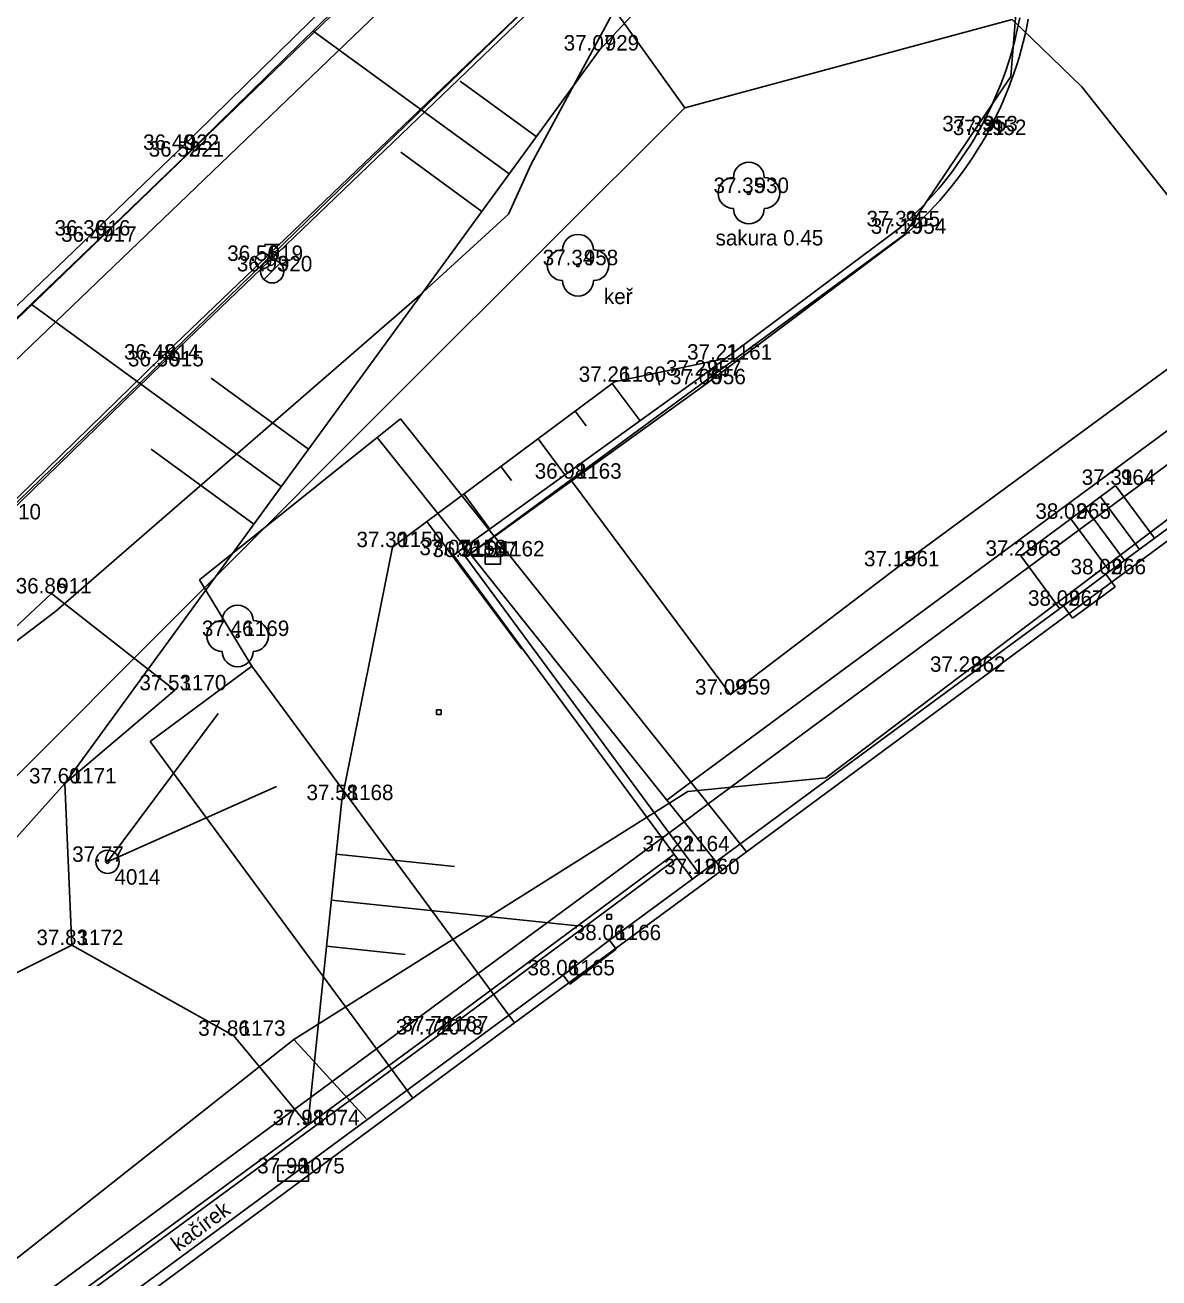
# Model space of a CAD drawing. Extents: x -609709 to -609357, y -1051535 to -1051131.
# Drawn here: x -609603.24 to -609584.85, y -1051267.96 to -1051247.66 of the extents above; entities that cross this region are included whole.
import ezdxf

# ---------------------------------------------------------------- set-up
doc = ezdxf.new("R2010")
doc.units = 0
for name, color, linetype in [('Vrstva 1', 7, 'Continuous'), ('Vrstva 10', 7, 'Continuous'), ('Vrstva 12', 7, 'Continuous'), ('Vrstva 15', 7, 'Continuous'), ('Vrstva 17', 7, 'Continuous'), ('Vrstva 18', 7, 'Continuous'), ('Vrstva 2', 7, 'Continuous'), ('Vrstva 3', 7, 'Continuous'), ('Vrstva 4', 7, 'Continuous'), ('Vrstva 5', 7, 'Continuous'), ('Vrstva 6', 7, 'Continuous'), ('Vrstva 7', 7, 'Continuous'), ('Vrstva 8', 7, 'Continuous'), ('Vrstva 9', 7, 'Continuous')]:
    doc.layers.add(name, color=color, linetype=linetype)

msp = doc.modelspace()

# ---------------------------------------------------------------- linework, layer by layer
at = {"layer": 'Vrstva 1'}
for p, q in [((-609593.93, -1051248.07), (-609593.93, -1051248.07)), ((-609587.79, -1051249.38), (-609587.79, -1051249.38)), ((-609587.65, -1051249.44), (-609587.65, -1051249.44)), ((-609600.74, -1051249.68), (-609600.74, -1051249.68)), ((-609600.66, -1051249.79), (-609600.66, -1051249.79)), ((-609591.5, -1051250.38), (-609591.5, -1051250.38)), ((-609602.18, -1051251.07), (-609602.18, -1051251.07)), ((-609589.05, -1051250.92), (-609589.05, -1051250.92)), ((-609588.95, -1051251.04), (-609588.95, -1051251.04)), ((-609602.08, -1051251.17), (-609602.08, -1051251.17)), ((-609599.38, -1051251.48), (-609599.38, -1051251.48)), ((-609599.23, -1051251.65), (-609599.23, -1051251.65)), ((-609594.27, -1051251.55), (-609594.27, -1051251.55)), ((-609601.06, -1051253.08), (-609601.06, -1051253.08)), ((-609591.96, -1051253.08), (-609591.96, -1051253.08)), ((-609600.99, -1051253.19), (-609600.99, -1051253.19)), ((-609592.27, -1051253.34), (-609592.27, -1051253.34)), ((-609593.68, -1051253.44), (-609593.68, -1051253.44)), ((-609592.2, -1051253.48), (-609592.2, -1051253.48)), ((-609594.4, -1051255.01), (-609594.4, -1051255.01)), ((-609585.56, -1051255.11), (-609585.56, -1051255.11)), ((-609586.28, -1051255.66), (-609586.28, -1051255.66)), ((-609597.28, -1051256.12), (-609597.28, -1051256.12)), ((-609596.27, -1051256.25), (-609596.27, -1051256.25)), ((-609596.09, -1051256.28), (-609596.09, -1051256.28)), ((-609595.65, -1051256.27), (-609595.65, -1051256.27)), ((-609587.09, -1051256.26), (-609587.09, -1051256.26)), ((-609589.06, -1051256.43), (-609589.06, -1051256.43)), ((-609585.71, -1051256.56), (-609585.71, -1051256.56)), ((-609602.81, -1051256.87), (-609602.81, -1051256.87)), ((-609586.4, -1051257.07), (-609586.4, -1051257.07)), ((-609599.79, -1051257.56), (-609599.79, -1051257.56)), ((-609587.99, -1051258.14), (-609587.99, -1051258.14)), ((-609600.81, -1051258.44), (-609600.81, -1051258.44)), ((-609591.8, -1051258.51), (-609591.8, -1051258.51)), ((-609602.59, -1051259.95), (-609602.59, -1051259.95)), ((-609598.1, -1051260.22), (-609598.1, -1051260.22)), ((-609592.65, -1051261.05), (-609592.65, -1051261.05)), ((-609601.9, -1051261.22), (-609601.9, -1051261.22)), ((-609592.3, -1051261.42), (-609592.3, -1051261.42)), ((-609602.48, -1051262.57), (-609602.48, -1051262.57)), ((-609593.76, -1051262.49), (-609593.76, -1051262.49)), ((-609594.51, -1051263.06), (-609594.51, -1051263.06)), ((-609599.85, -1051264.04), (-609599.85, -1051264.04)), ((-609596.65, -1051264.02), (-609596.65, -1051264.02)), ((-609596.56, -1051263.97), (-609596.56, -1051263.97)), ((-609598.65, -1051265.49), (-609598.65, -1051265.49)), ((-609598.89, -1051266.27), (-609598.89, -1051266.27))]:
    msp.add_line(p, q, dxfattribs=at)
at = {"layer": 'Vrstva 10'}
for p, q in [((-609622.18, -1051273.63), (-609589.38, -1051241.83)), ((-609623.53, -1051271.88), (-609592.58, -1051242.01)), ((-609587.25, -1051248.49), (-609587.01, -1051245.46)), ((-609588.98, -1051251.06), (-609587.25, -1051248.49)), ((-609595.63, -1051255.94), (-609588.98, -1051251.06)), ((-609592.44, -1051259.93), (-609583.52, -1051253.35)), ((-609592.16, -1051260.28), (-609583.26, -1051253.71)), ((-609597.53, -1051254.34), (-609597.15, -1051254.04)), ((-609597.15, -1051254.04), (-609595.63, -1051255.94)), ((-609600.41, -1051256.65), (-609597.53, -1051254.34)), ((-609597.53, -1051254.34), (-609596.02, -1051256.23)), ((-609591.54, -1051261.06), (-609582.68, -1051254.52)), ((-609596.02, -1051256.23), (-609595.63, -1051255.94)), ((-609595.63, -1051255.94), (-609592.44, -1051259.93)), ((-609596.02, -1051256.23), (-609592.83, -1051260.22)), ((-609600.41, -1051256.65), (-609599.56, -1051258.05)), ((-609601.21, -1051259.27), (-609599.56, -1051258.05)), ((-609599.56, -1051258.05), (-609595.89, -1051263.03)), ((-609596.565, -1051258.755), (-609596.49, -1051258.755)), ((-609596.565, -1051258.83), (-609596.565, -1051258.755)), ((-609596.49, -1051258.83), (-609596.565, -1051258.83)), ((-609596.49, -1051258.755), (-609596.49, -1051258.83)), ((-609601.21, -1051259.27), (-609597.54, -1051264.25)), ((-609592.83, -1051260.22), (-609592.44, -1051259.93)), ((-609592.44, -1051259.93), (-609592.16, -1051260.28)), ((-609592.83, -1051260.22), (-609592.55, -1051260.57)), ((-609592.55, -1051260.57), (-609592.16, -1051260.28)), ((-609592.16, -1051260.28), (-609591.54, -1051261.06)), ((-609595.89, -1051263.03), (-609592.55, -1051260.57)), ((-609592.55, -1051260.57), (-609591.93, -1051261.35)), ((-609591.93, -1051261.35), (-609591.54, -1051261.06)), ((-609595.3, -1051263.83), (-609591.93, -1051261.35)), ((-609593.805, -1051262.075), (-609593.73, -1051262.075)), ((-609593.805, -1051262.15), (-609593.805, -1051262.075)), ((-609593.73, -1051262.075), (-609593.73, -1051262.15)), ((-609593.73, -1051262.15), (-609593.805, -1051262.15)), ((-609597.54, -1051264.25), (-609595.89, -1051263.03)), ((-609595.89, -1051263.03), (-609595.3, -1051263.83)), ((-609596.95, -1051265.05), (-609595.3, -1051263.83)), ((-609613.41, -1051275.95), (-609597.54, -1051264.25)), ((-609597.54, -1051264.25), (-609596.95, -1051265.05)), ((-609612.49, -1051276.52), (-609596.95, -1051265.05))]:
    msp.add_line(p, q, dxfattribs=at)
at = {"layer": 'Vrstva 12'}
for points in [[(-609574.91, -1051248.7), (-609578.66, -1051251.06), (-609581, -1051253.08), (-609583.53, -1051254.78), (-609590.25, -1051259.86), (-609592.49, -1051260.08), (-609598.88, -1051264.1), (-609597.705, -1051265.378)], [(-609598.88, -1051264.1), (-609604.42, -1051268.47), (-609611.68, -1051274.04), (-609616.21, -1051277.75), (-609621.57, -1051284.12), (-609621.25, -1051285.42), (-609619.8, -1051287.45), (-609615.97, -1051291.57), (-609612.96, -1051295.31), (-609611.54, -1051298.14), (-609609.99, -1051301.94), (-609609.26, -1051303.04), (-609608.61, -1051303.76)]]:
    msp.add_lwpolyline(points, dxfattribs=at)
at = {"layer": 'Vrstva 15'}
for points in [[(-609537.51, -1051208.58), (-609541.98, -1051211.54), (-609559.34, -1051222.57), (-609563.62, -1051224.83), (-609573.15, -1051229.82), (-609581.51, -1051234.92), (-609583.83, -1051237.49), (-609593.84, -1051247.18), (-609592.54, -1051249), (-609587.23, -1051247.57), (-609586.1, -1051248.66), (-609581.84, -1051254.04), (-609580.215, -1051257.976)], [(-609618.56, -1051272.15), (-609610.34, -1051264.5), (-609607, -1051260.39), (-609602.74, -1051257.16), (-609596.84, -1051252.04), (-609595.4, -1051250.72), (-609595.03, -1051249.91), (-609593.64, -1051247.34), (-609592.3, -1051245.79), (-609590.65, -1051244.31), (-609589.61, -1051243.13), (-609589.45, -1051242.87), (-609588.61, -1051241.92), (-609583.43, -1051237.16), (-609581.27, -1051235.22), (-609579.94, -1051234.39), (-609575.07, -1051232.15), (-609567.92, -1051226.6)], [(-609592.54, -1051249), (-609597.09, -1051253.54), (-609603.86, -1051260.31), (-609608.84, -1051264.59), (-609616.08, -1051271.44), (-609620.11, -1051274.18), (-609621.01, -1051275.83), (-609623.48, -1051278.12), (-609624.89, -1051278.61), (-609626.41, -1051281.76), (-609625.78, -1051282.81), (-609616.94, -1051293.56), (-609613.57, -1051297.39), (-609614.852, -1051298.693)]]:
    msp.add_lwpolyline(points, dxfattribs=at)
at = {"layer": 'Vrstva 17'}
msp.add_lwpolyline([(-609531.786, -1051180.515), (-609532.61, -1051181.07), (-609528.54, -1051185.58), (-609545.95, -1051201.69), (-609546.72, -1051202.27), (-609551.04, -1051206.15), (-609565.42, -1051219.63), (-609579.77, -1051233.3), (-609583.56, -1051235.84), (-609591.75, -1051241.92), (-609609.05, -1051258.52), (-609618.01, -1051267.11), (-609626.05, -1051275.26), (-609630.23, -1051279.58), (-609635.78, -1051285.7), (-609642.85, -1051291.4), (-609672.95, -1051307.23)], dxfattribs=at)
at = {"layer": 'Vrstva 18'}
for points in [[(-609601.9, -1051261.22), (-609600.104, -1051258.817)], [(-609601.9, -1051261.22), (-609599.159, -1051260)]]:
    msp.add_lwpolyline(points, dxfattribs=at)
for radius in [0.188, 0.025]:
    msp.add_circle((-609601.9, -1051261.22), radius, dxfattribs=at)
at = {"layer": 'Vrstva 4'}
for p, q in [((-609596.602, -1051264.084), (-609592.665, -1051261.161)), ((-609598.603, -1051265.554), (-609596.602, -1051264.084)), ((-609602.602, -1051268.489), (-609598.603, -1051265.555))]:
    msp.add_line(p, q, dxfattribs=at)
for points in [[(-609601.06, -1051253.08), (-609594.93, -1051247.2), (-609590.24, -1051242.69), (-609589.342, -1051241.842)], [(-609601.005, -1051253.138), (-609594.875, -1051247.258), (-609590.185, -1051242.748), (-609589.263, -1051241.878)], [(-609602.18, -1051251.07), (-609600.74, -1051249.68), (-609596.46, -1051245.49), (-609592.84, -1051242.03)], [(-609602.083, -1051251.171), (-609600.642, -1051249.78), (-609596.363, -1051245.591), (-609592.752, -1051242.14)], [(-609594.374, -1051255.045), (-609591.8, -1051258.51), (-609589.06, -1051256.43), (-609583.93, -1051252.66), (-609583.27, -1051253.59), (-609579.32, -1051250.66), (-609579.218, -1051250.796)], [(-609602.18, -1051251.07), (-609605.07, -1051253.83), (-609609.18, -1051257.81), (-609614.3, -1051258.05), (-609615.05, -1051258.25), (-609617.76, -1051260.87), (-609618.44, -1051261.52), (-609620.65, -1051263.68), (-609621.37, -1051264.36), (-609621.71, -1051264.87), (-609623.18, -1051267.49), (-609624.27, -1051269.45), (-609624.77, -1051270.32), (-609626.73, -1051273.81), (-609627.2, -1051274.7), (-609627.81, -1051275.78), (-609632.5, -1051279.47)], [(-609589.038, -1051250.931), (-609592.283, -1051253.367), (-609596.287, -1051256.249), (-609592.413, -1051261.503)], [(-609588.95, -1051251.04), (-609592.2, -1051253.48), (-609596.09, -1051256.28), (-609592.3, -1051261.42)], [(-609602.083, -1051251.171), (-609604.973, -1051253.931), (-609609.121, -1051257.947), (-609614.278, -1051258.189), (-609614.979, -1051258.376), (-609617.663, -1051260.971), (-609618.343, -1051261.621), (-609620.553, -1051263.781), (-609621.262, -1051264.451), (-609621.591, -1051264.943), (-609623.058, -1051267.558), (-609624.148, -1051269.519), (-609624.648, -1051270.389), (-609626.607, -1051273.877), (-609627.077, -1051274.767), (-609627.702, -1051275.873), (-609632.413, -1051279.58)], [(-609601.06, -1051253.08), (-609604.02, -1051255.96), (-609607.62, -1051259.41), (-609610.87, -1051262.54), (-609616.26, -1051267.77), (-609619.52, -1051270.88), (-609621.59, -1051272.88)], [(-609601.004, -1051253.137), (-609603.964, -1051256.018), (-609607.565, -1051259.468), (-609610.814, -1051262.598), (-609616.205, -1051267.828), (-609619.465, -1051270.938), (-609621.528, -1051272.931)], [(-609602.63, -1051268.41), (-609598.65, -1051265.49), (-609596.65, -1051264.02), (-609592.713, -1051261.096)]]:
    msp.add_lwpolyline(points, dxfattribs=at)
for radius, start, end in [(5.945, 311.2028, 349.5269), (6.085, 311.1529, 349.5703)]:
    msp.add_arc((-609592.954, -1051246.458), radius, start, end, dxfattribs=at)
at = {"layer": 'Vrstva 5'}
for p, q in [((-609599.355, -1051251.212), (-609599.105, -1051251.212)), ((-609599.23, -1051251.462), (-609599.23, -1051251.212)), ((-609599.098, -1051251.517), (-609599.363, -1051251.782)), ((-609595.775, -1051256.27), (-609595.525, -1051256.27))]:
    msp.add_line(p, q, dxfattribs=at)
for points in [[(-609595.775, -1051256.145), (-609595.525, -1051256.145), (-609595.525, -1051256.395), (-609595.775, -1051256.395)], [(-609599.14, -1051266.145), (-609598.64, -1051266.145), (-609598.64, -1051266.395), (-609599.14, -1051266.395)]]:
    msp.add_lwpolyline(points, close=True, dxfattribs=at)
for centre, radius in [((-609599.38, -1051251.48), 0.125), ((-609599.23, -1051251.65), 0.188)]:
    msp.add_circle(centre, radius, dxfattribs=at)
at = {"layer": 'Vrstva 6'}
for points in [[(-609610.31, -1051288.53), (-609610.4, -1051286.73), (-609612.71, -1051282.35), (-609615.84, -1051278.39), (-609617.55, -1051275.92), (-609615.49, -1051274.55), (-609612.49, -1051270.95), (-609610.45, -1051268.68), (-609607.94, -1051265.3), (-609606.28, -1051264.06), (-609602.59, -1051259.95), (-609593.93, -1051248.07), (-609590.64, -1051244.54), (-609589.23, -1051241.892)], [(-609591.96, -1051253.08), (-609593.68, -1051253.44), (-609597.28, -1051256.12), (-609598.1, -1051260.22), (-609598.65, -1051265.49)]]:
    msp.add_lwpolyline(points, dxfattribs=at)
at = {"layer": 'Vrstva 7'}
for points in [[(-609602.81, -1051256.87), (-609609.78, -1051263.4), (-609613.32, -1051266.99), (-609616.49, -1051269.92), (-609618.44, -1051272.03), (-609620.38, -1051273.6), (-609620.1, -1051276.08), (-609618.51, -1051277.17), (-609616.15, -1051276.49)], [(-609612.91, -1051269.83), (-609607.94, -1051265.3), (-609602.48, -1051262.57), (-609602.59, -1051259.95), (-609600.81, -1051258.44), (-609602.81, -1051256.87)], [(-609598.65, -1051265.49), (-609599.85, -1051264.04), (-609602.48, -1051262.57)]]:
    msp.add_lwpolyline(points, dxfattribs=at)
for centre in [(-609591.5, -1051250.38), (-609594.27, -1051251.55), (-609599.79, -1051257.56)]:
    msp.add_circle(centre, 0.025, dxfattribs=at)
for centre, start, end in [((-609591.5, -1051250.13), 0, 180), ((-609591.75, -1051250.38), 90, 270), ((-609591.25, -1051250.38), 270, 90), ((-609591.5, -1051250.63), 180, 0), ((-609594.27, -1051251.3), 0, 180), ((-609594.52, -1051251.55), 90, 270), ((-609594.02, -1051251.55), 270, 90), ((-609594.27, -1051251.8), 180, 0), ((-609599.79, -1051257.31), 0, 180), ((-609600.04, -1051257.56), 90, 270), ((-609599.54, -1051257.56), 270, 90), ((-609599.79, -1051257.81), 180, 0)]:
    msp.add_arc(centre, 0.25, start, end, dxfattribs=at)
at = {"layer": 'Vrstva 8'}
for p, q in [((-609595.388, -1051250.071), (-609598.57, -1051247.751)), ((-609594.947, -1051249.465), (-609596.179, -1051248.567)), ((-609595.83, -1051250.677), (-609597.143, -1051249.719)), ((-609599.083, -1051255.139), (-609603.141, -1051252.181)), ((-609592.99, -1051253.296), (-609592.947, -1051253.497)), ((-609598.641, -1051254.533), (-609600.221, -1051253.382)), ((-609593.716, -1051253.467), (-609593.264, -1051254.073)), ((-609594.317, -1051253.915), (-609594.14, -1051254.153)), ((-609594.919, -1051254.362), (-609594.482, -1051254.95)), ((-609599.525, -1051255.745), (-609601.192, -1051254.53)), ((-609595.521, -1051254.81), (-609595.349, -1051255.041)), ((-609596.122, -1051255.258), (-609595.699, -1051255.826)), ((-609596.724, -1051255.706), (-609595.183, -1051257.776)), ((-609598.192, -1051261.098), (-609596.271, -1051261.298)), ((-609598.269, -1051261.844), (-609594.28, -1051262.26)), ((-609598.347, -1051262.59), (-609597.076, -1051262.722))]:
    msp.add_line(p, q, dxfattribs=at)
at = {"layer": 'Vrstva 9'}
for p, q in [((-609585.798, -1051255.303), (-609585.166, -1051256.158)), ((-609586.039, -1051255.482), (-609585.407, -1051256.336))]:
    msp.add_line(p, q, dxfattribs=at)
for points in [[(-609585.71, -1051256.56), (-609582.6, -1051254.26), (-609581.18, -1051256.2), (-609580.73, -1051256.82)], [(-609586.28, -1051255.66), (-609585.552, -1051255.121)], [(-609585.552, -1051255.121), (-609584.92, -1051255.976)], [(-609586.28, -1051255.66), (-609587.09, -1051256.26)], [(-609586.28, -1051255.66), (-609585.648, -1051256.514)], [(-609587.09, -1051256.26), (-609586.461, -1051257.115)], [(-609585.71, -1051256.56), (-609586.4, -1051257.07)], [(-609585.561, -1051256.761), (-609585.71, -1051256.56)], [(-609586.251, -1051257.271), (-609585.561, -1051256.761)], [(-609593.76, -1051262.49), (-609586.4, -1051257.07)], [(-609586.251, -1051257.271), (-609586.4, -1051257.07)], [(-609593.76, -1051262.49), (-609594.51, -1051263.06)], [(-609594.403, -1051263.205), (-609593.653, -1051262.635)], [(-609593.76, -1051262.49), (-609593.653, -1051262.635)], [(-609612.85, -1051276.57), (-609594.51, -1051263.06)], [(-609594.51, -1051263.06), (-609594.403, -1051263.205)]]:
    msp.add_lwpolyline(points, dxfattribs=at)

# ---------------------------------------------------------------- texts
at = {"layer": 'Vrstva 18'}
msp.add_text(' 4014', height=0.25, dxfattribs=at).set_placement((-609601.88, -1051261.59))
at = {"layer": 'Vrstva 2'}
for s, p in [(' 929', (-609593.93, -1051248.07)), (' 953', (-609587.79, -1051249.38)), (' 952', (-609587.65, -1051249.44)), (' 922', (-609600.74, -1051249.68)), (' 921', (-609600.66, -1051249.79)), (' 930', (-609591.5, -1051250.38)), (' 955', (-609589.05, -1051250.92)), (' 916', (-609602.18, -1051251.07)), (' 954', (-609588.95, -1051251.04)), (' 917', (-609602.08, -1051251.17)), (' 919', (-609599.38, -1051251.48)), (' 958', (-609594.27, -1051251.55)), (' 920', (-609599.23, -1051251.65)), (' 914', (-609601.06, -1051253.08)), (' 915', (-609600.99, -1051253.19)), (' 1161', (-609591.96, -1051253.08)), (' 957', (-609592.27, -1051253.34)), (' 1160', (-609593.68, -1051253.44)), (' 956', (-609592.2, -1051253.48)), (' 1163', (-609594.4, -1051255.01)), (' 964', (-609585.56, -1051255.11)), (' 910', (-609603.63, -1051255.67)), (' 965', (-609586.28, -1051255.66)), (' 1159', (-609597.28, -1051256.12)), (' 1158', (-609596.27, -1051256.25)), (' 1157', (-609596.09, -1051256.28)), (' 1162', (-609595.65, -1051256.27)), (' 961', (-609589.06, -1051256.43)), (' 963', (-609587.09, -1051256.26)), (' 966', (-609585.71, -1051256.56)), (' 911', (-609602.81, -1051256.87)), (' 967', (-609586.4, -1051257.07)), (' 1169', (-609599.79, -1051257.56)), (' 962', (-609587.99, -1051258.14)), (' 1170', (-609600.81, -1051258.44)), (' 959', (-609591.8, -1051258.51)), (' 1171', (-609602.59, -1051259.95)), (' 1168', (-609598.1, -1051260.22)), (' 1164', (-609592.65, -1051261.05)), (' 960', (-609592.3, -1051261.42)), (' 1166', (-609593.76, -1051262.49)), (' 1172', (-609602.48, -1051262.57)), (' 1165', (-609594.51, -1051263.06)), (' 1173', (-609599.85, -1051264.04)), (' 1073', (-609596.65, -1051264.02)), (' 1167', (-609596.56, -1051263.97)), (' 1074', (-609598.65, -1051265.49)), (' 1075', (-609598.89, -1051266.27))]:
    msp.add_text(s, height=0.25, dxfattribs=at).set_placement(p)
at = {"layer": 'Vrstva 3'}
for s, p in [('37.07', (-609594.503, -1051248.07)), ('37.33', (-609588.363, -1051249.38)), ('37.21', (-609588.192, -1051249.44)), ('36.40', (-609601.323, -1051249.68)), ('36.52', (-609601.233, -1051249.79)), ('37.35', (-609592.073, -1051250.38)), ('37.31', (-609589.592, -1051250.92)), ('36.36', (-609602.759, -1051251.07)), ('37.19', (-609589.523, -1051251.04)), ('36.47', (-609602.653, -1051251.17)), ('36.56', (-609599.959, -1051251.48)), ('37.34', (-609594.843, -1051251.55)), ('36.93', (-609599.803, -1051251.65)), ('36.48', (-609601.633, -1051253.08)), ('36.56', (-609601.569, -1051253.19)), ('37.21', (-609592.502, -1051253.08)), ('37.22', (-609592.843, -1051253.34)), ('37.26', (-609594.259, -1051253.44)), ('37.06', (-609592.779, -1051253.48)), ('36.98', (-609594.973, -1051255.01)), ('37.31', (-609586.102, -1051255.11)), ('38.02', (-609586.853, -1051255.66)), ('37.30', (-609597.863, -1051256.12)), ('37.07', (-609596.843, -1051256.25)), ('36.91', (-609596.632, -1051256.28)), ('36.94', (-609596.223, -1051256.27)), ('37.15', (-609589.633, -1051256.43)), ('37.23', (-609587.663, -1051256.26)), ('38.02', (-609586.283, -1051256.56)), ('36.86', (-609603.389, -1051256.87)), ('38.02', (-609586.973, -1051257.07)), ('37.46', (-609600.369, -1051257.56)), ('37.22', (-609588.563, -1051258.14)), ('37.53', (-609601.383, -1051258.44)), ('37.09', (-609592.373, -1051258.51)), ('37.60', (-609603.173, -1051259.95)), ('37.58', (-609598.673, -1051260.22)), ('37.22', (-609593.223, -1051261.05)), ('37.77', (-609602.473, -1051261.22)), ('37.12', (-609592.873, -1051261.42)), ('38.06', (-609594.339, -1051262.49)), ('37.83', (-609603.053, -1051262.57)), ('38.06', (-609595.089, -1051263.06)), ('37.86', (-609600.429, -1051264.04)), ('37.72', (-609597.223, -1051264.02)), ('37.72', (-609597.133, -1051263.97)), ('37.98', (-609599.223, -1051265.49)), ('37.90', (-609599.473, -1051266.27))]:
    msp.add_text(s, height=0.25, dxfattribs=at).set_placement(p)
at = {"layer": 'Vrstva 5'}
msp.add_text('kačírek', height=0.25, rotation=36.3769, dxfattribs=at).set_placement((-609600.752, -1051267.547))
at = {"layer": 'Vrstva 7'}
for s, p in [('sakura 0.45', (-609592.04, -1051251.23)), ('keř', (-609593.85, -1051252.18))]:
    msp.add_text(s, height=0.25, dxfattribs=at).set_placement(p)

doc.saveas('drawing.dxf')
